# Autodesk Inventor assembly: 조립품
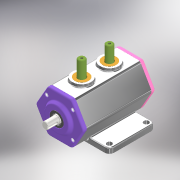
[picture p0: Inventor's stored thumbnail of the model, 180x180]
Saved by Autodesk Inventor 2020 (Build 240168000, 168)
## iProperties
Created: 2021-06
Part Number: 조립품
Document SubType Name: Assembly
Designer: 602-02
Author: 602-02
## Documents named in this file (11)
- C:\Users\602-02\Desktop\710606V1003\조립품.iam
- C:\Users\602-02\Desktop\710606V1003\본체.ipt
- C:\Users\602-02\Desktop\710606V1003\앞커버.ipt
- C:\Users\602-02\Desktop\710606V1003\뒷커버.ipt
- C:\Users\602-02\Desktop\710606V1003\부시.ipt
- C:\Users\602-02\Desktop\710606V1003\베어링 6203.ipt
- C:\Users\602-02\Desktop\710606V1003\오일실.ipt
- C:\Users\602-02\Desktop\710606V1003\편심축.ipt
- C:\Users\602-02\Desktop\710606V1003\베어링 6302.ipt
- C:\Users\602-02\Desktop\710606V1003\슬라이더.ipt
- C:\Users\602-02\Desktop\710606V1003\볼트 M4.ipt
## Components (10 placed, 3 different names)
1. 7-베어링 6203:1
2. 8-오일실:1
3. 9-M4-소켓머리:1
4. 9-M4-소켓머리:3
5. 9-M4-소켓머리:4
6. 9-M4-소켓머리:5
7. 9-M4-소켓머리:2
8. 9-M4-소켓머리:6
9. 9-M4-소켓머리:7
10. 9-M4-소켓머리:8
